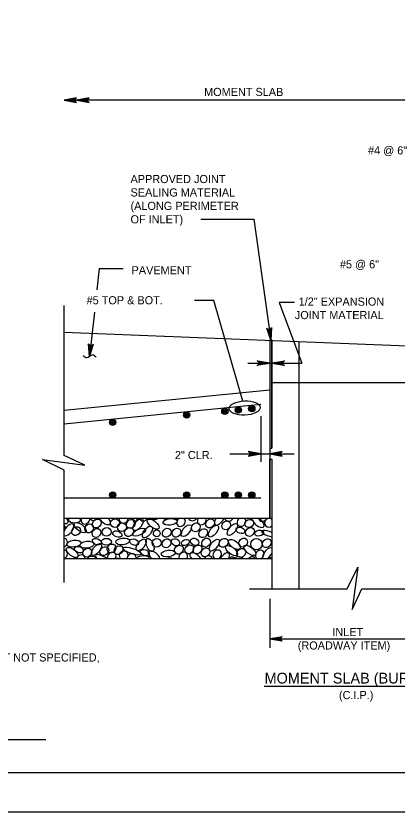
# Model space of a CAD drawing. Extents: x 638167 to 640248, y 296544 to 298920.
# Drawn here: x 639318.3 to 639462.1, y 296544.5 to 296845.2 of the extents above; entities that cross this region are included whole.
import ezdxf

# ---------------------------------------------------------------- set-up
doc = ezdxf.new("R2010")
doc.units = 0
for name, color, linetype in [('1', 7, 'Continuous'), ('50', 7, 'Continuous'), ('PLT-BNDY', 7, 'Continuous')]:
    doc.layers.add(name, color=color, linetype=linetype)

# ---------------------------------------------------------------- blocks, each defined once
blk = doc.blocks.new('BAR')
at = {"layer": '50'}
for radius in [2, 1.5, 1, 0.5]:
    blk.add_circle((0, 0), radius, dxfattribs=at)

msp = doc.modelspace()

# ---------------------------------------------------------------- linework, layer by layer
at = {"layer": '1'}
for p, q in [((639476.71, 296813.37), (639336.46, 296813.37)), ((639388.06, 296768.48), (639408.01, 296768.48)), ((639408.01, 296768.48), (639414.48, 296722.69)), ((639349.62, 296749.87), (639348.75, 296741.72)), ((639349.62, 296749.87), (639358.69, 296749.87)), ((639336.46, 296679.2), (639336.46, 296735.87)), ((639392.99, 296737.72), (639385.68, 296737.72)), ((639403.85, 296699.76), (639392.99, 296737.72)), ((639423.42, 296737.02), (639417.6, 296737.02)), ((639417.6, 296737.02), (639426.18, 296714)), ((639347.86, 296733.32), (639346.08, 296716.6)), ((639336.46, 296725.82), (639476.71, 296720.21)), ((639414.06, 296722.71), (639414.06, 296655.43)), ((639414.9, 296722.68), (639414.9, 296682)), ((639425.06, 296722.27), (639425.06, 296628.84)), ((639405.75, 296714), (639426.18, 296714)), ((639475.86, 296706.66), (639414.9, 296706.66)), ((639414.06, 296703.84), (639336.46, 296696.17)), ((639410.67, 296698.4), (639336.46, 296691.06)), ((639410.67, 296694.05), (639410.67, 296676.79)), ((639399.02, 296679.86), (639423.28, 296679.86)), ((639414.9, 296677.84), (639414.9, 296628.84)), ((639336.46, 296631.14), (639336.46, 296673.66)), ((639410.67, 296663.05), (639336.46, 296663.05)), ((639414.06, 296655.43), (639336.46, 296655.43)), ((639414.9, 296640.19), (639336.46, 296640.19)), ((639406.47, 296628.84), (639443.3, 296628.84)), ((639448.84, 296628.84), (639484.35, 296628.84)), ((639414.06, 296624.98), (639414.06, 296606.57)), ((639414.06, 296609.9), (639476.71, 296609.9)), ((639411.9, 296592.08), (639490.25, 296592.08)), ((639265.08, 296571.83), (639329.58, 296571.83)), ((639046.78, 296559.48), (639832.78, 296559.48))]:
    msp.add_line(p, q, dxfattribs=at)
for points in [[(639336.46, 296813.37), (639341.16, 296812.49), (639340.97, 296812.61), (639340.79, 296812.74), (639340.7, 296812.89), (639340.61, 296813.05), (639340.58, 296813.21), (639340.55, 296813.37), (639340.58, 296813.52), (639340.61, 296813.68), (639340.7, 296813.84), (639340.79, 296814), (639340.97, 296814.12), (639341.16, 296814.25), (639336.46, 296813.37), (639340.97, 296814.12), (639340.79, 296814), (639336.46, 296813.37), (639340.7, 296813.84), (639340.61, 296813.68), (639336.46, 296813.37), (639340.58, 296813.52), (639340.55, 296813.37), (639336.46, 296813.37), (639340.58, 296813.21), (639340.61, 296813.05), (639336.46, 296813.37), (639340.7, 296812.89), (639340.79, 296812.74), (639336.46, 296813.37), (639340.97, 296812.61)], [(639341.2, 296813.37), (639345.9, 296812.49), (639345.72, 296812.61), (639345.54, 296812.74), (639345.45, 296812.89), (639345.35, 296813.05), (639345.32, 296813.21), (639345.3, 296813.37), (639345.32, 296813.52), (639345.35, 296813.68), (639345.45, 296813.84), (639345.54, 296814), (639345.72, 296814.12), (639345.9, 296814.25), (639341.2, 296813.37), (639345.72, 296814.12), (639345.54, 296814), (639341.2, 296813.37), (639345.45, 296813.84), (639345.35, 296813.68), (639341.2, 296813.37), (639345.32, 296813.52), (639345.3, 296813.37), (639341.2, 296813.37), (639345.32, 296813.21), (639345.35, 296813.05), (639341.2, 296813.37), (639345.45, 296812.89), (639345.54, 296812.74), (639341.2, 296813.37), (639345.72, 296812.61)], [(639414.48, 296722.69), (639412.95, 296727.22), (639413.1, 296727.06), (639413.25, 296726.9), (639413.42, 296726.83), (639413.59, 296726.76), (639413.75, 296726.75), (639413.91, 296726.75), (639414.06, 296726.8), (639414.21, 296726.85), (639414.35, 296726.96), (639414.5, 296727.08), (639414.6, 296727.27), (639414.69, 296727.47), (639414.48, 296722.69), (639414.6, 296727.27), (639414.5, 296727.08), (639414.48, 296722.69), (639414.35, 296726.96), (639414.21, 296726.85), (639414.48, 296722.69), (639414.06, 296726.8), (639413.91, 296726.75), (639414.48, 296722.69), (639413.75, 296726.75), (639413.59, 296726.76), (639414.48, 296722.69), (639413.42, 296726.83), (639413.25, 296726.9), (639414.48, 296722.69), (639413.1, 296727.06)], [(639346.08, 296716.6), (639345.7, 296721.37), (639345.81, 296721.17), (639345.91, 296720.98), (639346.06, 296720.87), (639346.21, 296720.76), (639346.36, 296720.72), (639346.51, 296720.67), (639346.67, 296720.69), (639346.83, 296720.7), (639347, 296720.77), (639347.17, 296720.85), (639347.31, 296721.01), (639347.45, 296721.18), (639346.08, 296716.6), (639347.31, 296721.01), (639347.17, 296720.85), (639346.08, 296716.6), (639347, 296720.77), (639346.83, 296720.7), (639346.08, 296716.6), (639346.67, 296720.69), (639346.51, 296720.67), (639346.08, 296716.6), (639346.36, 296720.72), (639346.21, 296720.76), (639346.08, 296716.6), (639346.06, 296720.87), (639345.91, 296720.98), (639346.08, 296716.6), (639345.81, 296721.17)], [(639414.06, 296714), (639409.36, 296713.12), (639409.54, 296713.25), (639409.72, 296713.37), (639409.81, 296713.53), (639409.91, 296713.69), (639409.93, 296713.85), (639409.96, 296714), (639409.93, 296714.16), (639409.91, 296714.32), (639409.81, 296714.48), (639409.72, 296714.63), (639409.54, 296714.76), (639409.36, 296714.88), (639414.06, 296714), (639409.54, 296714.76), (639409.72, 296714.63), (639414.06, 296714), (639409.81, 296714.48), (639409.91, 296714.32), (639414.06, 296714), (639409.93, 296714.16), (639409.96, 296714), (639414.06, 296714), (639409.93, 296713.85), (639409.91, 296713.69), (639414.06, 296714), (639409.81, 296713.53), (639409.72, 296713.37), (639414.06, 296714), (639409.54, 296713.25)], [(639414.9, 296714), (639419.6, 296714.88), (639419.42, 296714.76), (639419.24, 296714.63), (639419.15, 296714.48), (639419.05, 296714.32), (639419.02, 296714.16), (639419, 296714), (639419.02, 296713.85), (639419.05, 296713.69), (639419.15, 296713.53), (639419.24, 296713.37), (639419.42, 296713.25), (639419.6, 296713.12), (639414.9, 296714), (639419.42, 296713.25), (639419.24, 296713.37), (639414.9, 296714), (639419.15, 296713.53), (639419.05, 296713.69), (639414.9, 296714), (639419.02, 296713.85), (639419, 296714), (639414.9, 296714), (639419.02, 296714.16), (639419.05, 296714.32), (639414.9, 296714), (639419.15, 296714.48), (639419.24, 296714.63), (639414.9, 296714), (639419.42, 296714.76)], [(639336.46, 296673.66), (639328.29, 296677.66), (639344.28, 296675.48), (639336.46, 296679.2)], [(639410.67, 296679.86), (639405.97, 296680.74), (639406.15, 296680.62), (639406.33, 296680.49), (639406.43, 296680.33), (639406.52, 296680.17), (639406.55, 296680.02), (639406.57, 296679.86), (639406.55, 296679.7), (639406.52, 296679.54), (639406.43, 296679.39), (639406.33, 296679.23), (639406.15, 296679.1), (639405.97, 296678.98), (639410.67, 296679.86), (639406.15, 296679.1), (639406.33, 296679.23), (639410.67, 296679.86), (639406.43, 296679.39), (639406.52, 296679.54), (639410.67, 296679.86), (639406.55, 296679.7), (639406.57, 296679.86), (639410.67, 296679.86), (639406.55, 296680.02), (639406.52, 296680.17), (639410.67, 296679.86), (639406.43, 296680.33), (639406.33, 296680.49), (639410.67, 296679.86), (639406.15, 296680.62)], [(639414.06, 296679.86), (639418.75, 296678.98), (639418.57, 296679.1), (639418.39, 296679.23), (639418.3, 296679.39), (639418.21, 296679.54), (639418.18, 296679.7), (639418.15, 296679.86), (639418.18, 296680.02), (639418.21, 296680.17), (639418.3, 296680.33), (639418.39, 296680.49), (639418.57, 296680.62), (639418.75, 296680.74), (639414.06, 296679.86), (639418.57, 296680.62), (639418.39, 296680.49), (639414.06, 296679.86), (639418.3, 296680.33), (639418.21, 296680.17), (639414.06, 296679.86), (639418.18, 296680.02), (639418.15, 296679.86), (639414.06, 296679.86), (639418.18, 296679.7), (639418.21, 296679.54), (639414.06, 296679.86), (639418.3, 296679.39), (639418.39, 296679.23), (639414.06, 296679.86), (639418.57, 296679.1)], [(639443.3, 296628.84), (639447.3, 296637), (639445.12, 296621.02), (639448.84, 296628.84)], [(639414.06, 296609.9), (639418.75, 296610.78), (639418.57, 296610.66), (639418.39, 296610.53), (639418.3, 296610.37), (639418.21, 296610.22), (639418.18, 296610.06), (639418.15, 296609.9), (639418.18, 296609.74), (639418.21, 296609.59), (639418.3, 296609.43), (639418.39, 296609.27), (639418.57, 296609.15), (639418.75, 296609.02), (639414.06, 296609.9), (639418.57, 296609.15), (639418.39, 296609.27), (639414.06, 296609.9), (639418.3, 296609.43), (639418.21, 296609.59), (639414.06, 296609.9), (639418.18, 296609.74), (639418.15, 296609.9), (639414.06, 296609.9), (639418.18, 296610.06), (639418.21, 296610.22), (639414.06, 296609.9), (639418.3, 296610.37), (639418.39, 296610.53), (639414.06, 296609.9), (639418.57, 296610.66)]]:
    msp.add_lwpolyline(points, dxfattribs=at)
for points in [[(639414.9, 296722.68), (639414.06, 296722.71), (639414.06, 296682), (639414.9, 296682)], [(639414.06, 296677.84), (639414.9, 296677.84), (639414.9, 296655.43), (639414.06, 296655.43)]]:
    msp.add_lwpolyline(points, close=True, dxfattribs=at)
msp.add_circle((639409.01, 296645.69), 2.13, dxfattribs=at)
for centre, major_axis, ratio in [((639404.6, 296697.11), (5.86, 0.22), 0.457892), ((639342.49, 296651.92), (-2.1, 1.65), 0.479042), ((639348.74, 296653.49), (1.2, 1.35), 0.844245), ((639355.62, 296653.64), (-1.58, -0.63), 0.948581), ((639358.27, 296652.05), (-1.58, -0.63), 0.948581), ((639361.6, 296653.36), (1.2, 1.35), 0.844245), ((639364.35, 296653.04), (-1.65, -2.1), 0.479042), ((639370.06, 296653.26), (-2.1, 1.65), 0.479042), ((639376.49, 296654.11), (-2.65, -0.32), 0.479042), ((639386.15, 296652.06), (1.2, 1.35), 0.844245), ((639391.54, 296653.52), (1.2, 1.35), 0.844245), ((639397.61, 296652.8), (1.2, 1.35), 0.844245), ((639399.96, 296651.22), (-1.65, -2.1), 0.479042), ((639406.3, 296653.53), (-1.57, -0.63), 0.87402), ((639340.96, 296650.62), (1.2, 1.35), 0.844245), ((639345.91, 296651.66), (1.2, 1.35), 0.844245), ((639348.65, 296649.91), (1.2, 1.35), 0.844245), ((639352.51, 296650.29), (-1.58, -0.63), 0.948581), ((639356.54, 296649.49), (1.65, -0.58), 0.646802), ((639360.93, 296650.27), (1.2, 1.35), 0.844245), ((639364.76, 296650.22), (2.45, 1.04), 0.422273), ((639367.89, 296650.26), (-1.65, -2.1), 0.479042), ((639371.4, 296649.77), (0, 1.28), 0.982495), ((639375.17, 296650), (1.2, 1.35), 0.844245), ((639378.86, 296650.02), (1.2, 1.35), 0.844245), ((639382.57, 296650.77), (-1.65, -2.1), 0.479042), ((639388.95, 296649.84), (1.2, 1.35), 0.844245), ((639392.83, 296650.62), (-1.65, -2.1), 0.479042), ((639403.01, 296650.87), (1.65, -0.58), 0.646802), ((639406.59, 296650.3), (1.2, 1.35), 0.844245), ((639410.07, 296649.87), (1.65, 0.33), 0.666084), ((639348.83, 296646.6), (1.65, -0.58), 0.646802), ((639352.42, 296646.61), (1.88, 0), 0.671766), ((639358.55, 296646.71), (-2.65, -0.32), 0.479042), ((639362.92, 296646.44), (1.65, -0.58), 0.646802), ((639365.49, 296645.4), (-1.65, -2.1), 0.479042), ((639368.83, 296645.35), (0.99, -2.48), 0.479042), ((639371.4, 296646.21), (-1.58, -0.63), 0.948581), ((639375.08, 296646.02), (1.2, 1.35), 0.844245), ((639378.47, 296646.41), (1.43, -0.74), 0.796199), ((639385.72, 296646.56), (1.43, -0.74), 0.796199), ((639390.02, 296646.26), (1.2, 1.35), 0.844245), ((639393.14, 296645.32), (-1.65, -2.1), 0.479042), ((639396.67, 296646.2), (1.2, 1.35), 0.844245), ((639400.7, 296645.59), (-2.1, 1.65), 0.479042), ((639404.04, 296646.27), (1.2, 1.35), 0.844245), ((639412.94, 296646.04), (1.2, 1.35), 0.844245), ((639339.49, 296642.56), (-2.1, 1.65), 0.479042), ((639340.17, 296645.89), (-2.65, -0.32), 0.479042), ((639341.97, 296643.61), (1.65, -0.58), 0.646802), ((639345.08, 296645.5), (-2.65, -0.32), 0.479042), ((639348.68, 296643.66), (-1.65, -2.1), 0.479042), ((639351.61, 296643.06), (1.2, 1.35), 0.844245), ((639354.31, 296644.05), (1.2, 1.35), 0.844245), ((639357, 296643.44), (1.2, 1.35), 0.844245), ((639362.08, 296643.07), (3.41, -1.15), 0.282192), ((639379.77, 296643.6), (1.2, 1.35), 0.844245), ((639382.24, 296646.34), (1.44, 0.65), 0.687276), ((639383.67, 296643.71), (1.2, 1.35), 0.844245), ((639386.82, 296643.69), (1.2, 1.35), 0.844245), ((639399.64, 296643.23), (-2.1, 1.65), 0.479042), ((639406.56, 296643.34), (-2.1, 1.65), 0.479042), ((639345.21, 296642.49), (1.2, 1.35), 0.844245), ((639366.86, 296642.48), (1.65, -0.58), 0.646802), ((639375.75, 296642.16), (-2.65, -0.32), 0.479042), ((639389.8, 296642.59), (1.2, 1.35), 0.844245), ((639403.32, 296642.35), (1.2, 1.35), 0.844245)]:
    msp.add_ellipse(centre, major_axis=major_axis, ratio=ratio, dxfattribs=at)
for centre, major_axis, ratio, start_param, end_param in [((639336.3, 296654.63), (1.65, -0.58), 0.646802, 5.03018, 7.511068), ((639340.34, 296654.92), (2.29, -0.09), 0.504072, 2.75806, 6.829452), ((639344.48, 296654.98), (1.2, 1.35), 0.844245, 1.944708, 5.626131), ((639347.76, 296656.32), (1.2, 1.35), 0.844245, 2.7635, 4.807339), ((639351.69, 296655.01), (-2.1, 1.65), 0.479042, 0.80365, 4.384477), ((639358.88, 296655.28), (-1.58, -0.63), 0.948581, 5.792273, 9.117671), ((639363.54, 296657.47), (0.54, 3.56), 0.282192, 2.221249, 4.148138), ((639366.55, 296656.15), (1.2, 1.35), 0.844245, 2.650508, 4.920331), ((639370.92, 296656.63), (1.2, 1.35), 0.844245, 3.000245, 4.570594), ((639375.94, 296657.26), (-1.65, -2.1), 0.479042, 6.021095, 7.26523), ((639378.82, 296656.7), (1.2, 1.35), 0.844245, 3.060195, 4.510644), ((639380.56, 296654.08), (1.2, 1.35), 0.844245, 1.287837, 6.283002), ((639385.08, 296656.18), (1.2, 1.35), 0.844245, 2.675208, 4.895631), ((639388.38, 296654.68), (1.2, 1.35), 0.844245, 1.754284, 5.816555), ((639395.12, 296655.16), (-1.65, -2.1), 0.479042, 4.950214, 8.336111), ((639398.74, 296656.02), (1.2, 1.35), 0.844245, 2.568896, 5.001943), ((639403.38, 296654.12), (1.2, 1.35), 0.844245, 1.324547, 6.246292), ((639409.71, 296653.97), (-2.1, 1.65), 0.479042, 0.165315, 5.022813), ((639411.5, 296655.96), (1.2, 1.35), 0.844245, 2.531775, 5.039064), ((639413.75, 296653.78), (-1.58, -0.63), 0.948581, 3.601492, 8.239665), ((639338.15, 296651.07), (-1.65, -2.1), 0.479042, 6.240884, 11.513614), ((639335.24, 296651.54), (1.2, 1.35), 0.844245, 4.774571, 6.272603), ((639413.85, 296649.61), (2.83, -0.91), 0.276285, 1.279185, 5.180359), ((639336.04, 296646.15), (1.2, 1.35), 0.844245, 4.209544, 6.837629), ((639336.07, 296641.73), (1.2, 1.35), 0.844245, 4.21609, 6.860534), ((639351.48, 296639.81), (3.16, -1.73), 0.282192, 1.291294, 4.039693), ((639354.41, 296640.95), (1.2, 1.35), 0.844245, 4.890713, 8.963312), ((639358.94, 296641.44), (-1.58, -0.63), 0.948581, 1.871353, 6.755405), ((639361.94, 296640.41), (-1.58, -0.63), 0.948581, 2.611641, 6.015118), ((639370.39, 296641.25), (-2.1, 1.65), 0.479042, 3.586638, 7.884675), ((639381.4, 296641), (1.2, 1.35), 0.844245, 4.857166, 8.996858), ((639386.11, 296640.51), (-2.1, 1.65), 0.479042, 4.000243, 7.47107), ((639394.23, 296641.78), (1.2, 1.35), 0.844245, 4.136341, 9.717683), ((639396.95, 296640.2), (-1.65, -2.1), 0.479042, 1.927425, 5.075715), ((639410.29, 296641.75), (1.2, 1.35), 0.844245, 4.191312, 9.662712), ((639413.23, 296642.03), (-1.65, -2.1), 0.479042, 3.123393, 6.028187), ((639413.23, 296642.03), (-1.65, -2.1), 0.479042, 0.974953, 2.064734), ((639340.01, 296638.35), (-2.1, 1.65), 0.479042, 5.428298, 6.043015), ((639342.68, 296639.93), (1.2, 1.35), 0.844245, 5.514517, 8.339507), ((639347.83, 296639.5), (-2.46, 1.05), 0.479042, 4.325848, 6.556596), ((639356.25, 296638.67), (1.2, 1.35), 0.844245, 0.203005, 1.084649), ((639366.05, 296639.96), (-2.65, -0.32), 0.479042, 3.072207, 5.861606), ((639376.14, 296638.73), (1.2, 1.35), 0.844245, 0.124773, 1.162881), ((639390.77, 296639.58), (1.2, 1.35), 0.844245, 5.731271, 8.122753), ((639399.6, 296639.13), (1.2, 1.35), 0.844245, 6.034654, 7.81937), ((639403.47, 296639.07), (-2.1, 1.65), 0.479042, 4.785375, 6.685938), ((639407.14, 296639.2), (1.2, 1.35), 0.844245, 5.989017, 7.865007), ((639413.93, 296638.87), (1.2, 1.35), 0.844245, 0.181011, 1.310312)]:
    msp.add_ellipse(centre, major_axis=major_axis, ratio=ratio, start_param=start_param, end_param=end_param, dxfattribs=at)
msp.add_spline([(639348.52, 296716.29), (639347.24, 296717.16), (639344.91, 296716.04), (639343.64, 296716.83)], degree=3, dxfattribs=at)
at = {"layer": 'PLT-BNDY'}
msp.add_lwpolyline([(639007.78, 297138.48), (639848.78, 297138.48), (639848.78, 296544.48), (639007.78, 296544.48)], close=True, dxfattribs=at)

# ---------------------------------------------------------------- block references
at = {"layer": '1', "xscale": 0.5953136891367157, "yscale": 0.5953136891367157, "rotation": -90.00000000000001}
for p in [(639397.12, 296695.87), (639402.2, 296696.37), (639407.28, 296696.87), (639354.79, 296691.68), (639382.73, 296694.44), (639354.79, 296664.24), (639382.73, 296664.24), (639397.12, 296664.24), (639402.2, 296664.24), (639407.28, 296664.24)]:
    msp.add_blockref('BAR', p, dxfattribs=at)

# ---------------------------------------------------------------- texts
at = {"layer": '1'}
for s, p in [('MOMENT SLAB', (639389.29, 296814.97)), ('#4 @ 6"', (639451.17, 296792.9)), ('APPROVED JOINT', (639361.51, 296782.08)), ('SEALING MATERIAL', (639361.51, 296777.01)), ('(ALONG PERIMETER', (639361.51, 296771.93)), ('OF INLET)', (639361.51, 296766.86)), ('#5 @ 6"', (639440.55, 296749.88)), ('PAVEMENT', (639361.9, 296747.62)), ('#5 TOP & BOT.', (639344.93, 296736.28)), ('1/2" EXPANSION', (639424.98, 296735.77)), ('JOINT MATERIAL', (639423.53, 296730.7)), ('2" CLR.', (639378.26, 296677.82)), ('INLET', (639437.69, 296610.95)), ('(ROADWAY ITEM)', (639424.64, 296605.88))]:
    msp.add_text(s, height=3.072, rotation=360, dxfattribs=at).set_placement(p)
for s, height, p in [(' FOR DIMENSIONS AND REINFORCEMENT NOT SPECIFIED,', 3.072, (639232.3, 296601.35)), ('MOMENT SLAB (BURIED)', 4.08, (639412.1, 296593.03)), ('(C.I.P.)', 3.072, (639440.19, 296587.15))]:
    msp.add_text(s, height=height, dxfattribs=at).set_placement(p)

doc.saveas('drawing.dxf')
